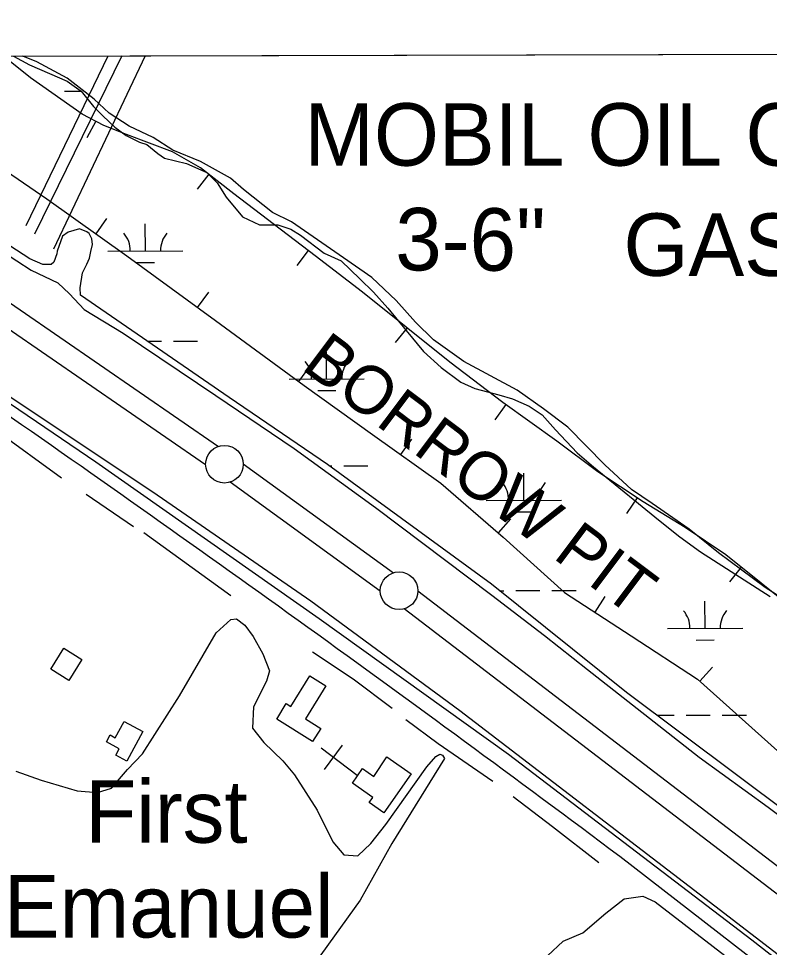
# Model space of a CAD drawing. Extents: x 3355724 to 3393621, y 594744 to 620174.
# Drawn here: x 3372282 to 3373280, y 617160 to 618395 of the extents above; entities that cross this region are included whole.
import ezdxf

# ---------------------------------------------------------------- set-up
doc = ezdxf.new("R2010")
doc.units = 0
for name, color, linetype in [('V-BLDG-OTLN', 7, 'Continuous'), ('V-BORW-IDEN', 7, 'Continuous'), ('V-BORW-LINE', 7, 'Continuous'), ('V-GRID-FRAM', 7, 'Continuous'), ('V-LEVE-TOET', 7, 'Continuous'), ('V-ROAD-CNTR', 7, 'Continuous'), ('V-SITE-OTLN', 7, 'Continuous'), ('V-SITE-OTLN-IDEN', 7, 'Continuous'), ('V-SITE-VEGE', 7, 'Continuous'), ('V-SURV-LINE', 7, 'Continuous'), ('V-TOPO-SHOR', 7, 'Continuous'), ('V-UTIL-IDEN', 7, 'Continuous'), ('V-UTIL-LINE', 7, 'Continuous'), ('V-WETL-SWMP', 7, 'Continuous')]:
    doc.layers.add(name, color=color, linetype=linetype)

msp = doc.modelspace()

# ---------------------------------------------------------------- linework, layer by layer
at = {"layer": 'V-BLDG-OTLN'}
for points in [[(3372342.6, 617558.2), (3372366.7, 617543.1), (3372349.2, 617515.1), (3372325.1, 617530.2)], [(3372673, 617434.2), (3372625.4, 617463.7), (3372638.2, 617484.5), (3372644.2, 617480.7), (3372669.4, 617521.3), (3372690.9, 617507.9), (3372663.8, 617464.2), (3372684.1, 617451.6)], [(3372447.6, 617447.5), (3372426.3, 617408.1), (3372411.8, 617415.9), (3372416.3, 617424.2), (3372399.1, 617433.6), (3372404.1, 617442.8), (3372411, 617439), (3372422.7, 617460.7)], [(3372771.6, 617413.7), (3372804.1, 617391.1), (3372767.9, 617339.3), (3372748.4, 617352.9), (3372753.3, 617359.8), (3372726, 617378.9), (3372739.3, 617398.1), (3372754.3, 617387.6)]]:
    msp.add_lwpolyline(points, close=True, dxfattribs=at)
at = {"layer": 'V-BORW-LINE'}
for p, q in [((3372385, 618258.4), (3372373.3, 618236.3)), ((3372535.1, 618187.9), (3372519.8, 618168.1)), ((3372385.5, 618108.6), (3372399.9, 618129)), ((3372667.2, 618086.4), (3372652, 618066.6)), ((3372520.4, 618010.9), (3372535.1, 618031)), ((3372798.6, 617984), (3372782.9, 617964.5)), ((3372654.7, 617912.3), (3372669.5, 617932.5)), ((3372930.1, 617881.8), (3372915.5, 617861.5)), ((3372790.3, 617815.6), (3372804.8, 617835.9)), ((3373104.2, 617758.1), (3373090.4, 617737.2)), ((3372920, 617711.3), (3372936.4, 617730.1)), ((3373242.6, 617665.7), (3373227, 617646.2)), ((3373048.5, 617605.9), (3373062.1, 617626.8)), ((3373187.6, 617514.3), (3373204.3, 617533))]:
    msp.add_line(p, q, dxfattribs=at)
for points in [[(3372997.7, 617833), (3372926, 617884.8), (3372855.5, 617938.1), (3372797.6, 617984.7), (3372739.6, 618031), (3372676.4, 618079.5), (3372613.1, 618127.9), (3372568.6, 618162.1), (3372524.1, 618196.4), (3372487.1, 618217.9), (3372426, 618240.8), (3372395.6, 618252.7), (3372367, 618267.9), (3372298.1, 618316), (3372262.3, 618344.7)], [(3372212.2, 618228.9), (3372319.8, 618155.2), (3372426.2, 618079.7), (3372544.2, 617993.4), (3372662, 617907), (3372752.8, 617842.2), (3372843.7, 617777.6), (3372926.5, 617705.6), (3373007.9, 617632.2), (3373096.5, 617574.7), (3373184.8, 617516.9), (3373291.1, 617421.7), (3373398.4, 617327.7), (3373494.7, 617255.3), (3373591.4, 617183.5), (3373670.1, 617126.2)], [(3373912.1, 617155.6), (3373904.1, 617173.1), (3373894, 617189.5), (3373865, 617228.4), (3373849, 617246.1), (3373830.8, 617262), (3373786.1, 617292.1), (3373739.7, 617318.7), (3373650.5, 617358.7), (3373606.5, 617379.4), (3373566, 617405.6), (3373489.8, 617466.6), (3373413.8, 617527.8), (3373318.2, 617605), (3373222.4, 617682), (3373168.4, 617718.4), (3373112.5, 617752.7), (3373052, 617792.5), (3372997.7, 617833)]]:
    msp.add_lwpolyline(points, dxfattribs=at)
at = {"layer": 'V-GRID-FRAM'}
msp.add_lwpolyline([(3359807.6, 618312.1), (3391397.2, 618394.8), (3391452.7, 600211.2), (3359847.2, 600128.5), (3359807.6, 618312.1)], dxfattribs=at)
at = {"layer": 'V-LEVE-TOET'}
for points in [[(3375825.8, 615008.1), (3375822, 615015.1), (3375811.4, 615025.5), (3375795.2, 615044.9), (3375674, 615158.8), (3375432.6, 615386.6), (3375213.6, 615584.5), (3374890.6, 615875.4), (3374636, 616096.2), (3374322.2, 616352.3), (3373944.2, 616649.4), (3373708.9, 616836.3), (3373573.2, 616934.7), (3373207.8, 617215.1), (3372868.9, 617474.7), (3372670.8, 617620.4), (3372460.9, 617765.4), (3372217.6, 617927), (3371905.3, 618137.9), (3371607.7, 618305.7), (3371539.6, 618342.8)], [(3372241.5, 618097.5), (3372299.3, 618060.5), (3372334.5, 618043.4), (3372350.3, 618029), (3372369.6, 618008.4), (3372421.3, 617976.8), (3372544.6, 617893.9), (3372648.6, 617823.3), (3372756.8, 617745.1), (3372911.1, 617628.5), (3372981.4, 617575), (3373038.6, 617529.8), (3373186.8, 617413.2), (3373278.4, 617346.7), (3373351.4, 617291.8), (3373522.3, 617160.8), (3373640.1, 617078.6), (3373834.5, 616920.1), (3373917.8, 616857.7), (3374126.6, 616693.8)]]:
    msp.add_lwpolyline(points, dxfattribs=at)
at = {"layer": 'V-ROAD-CNTR'}
msp.add_lwpolyline([(3373922.3, 616629.1), (3373081.6, 617281.1)], dxfattribs=at)
msp.add_arc((3355726.1, 594075.3), 28978, 53.20753, 55.24185, dxfattribs=at)
at = {"layer": 'V-SITE-OTLN'}
for p, q in [((3372712.4, 617429.1), (3372688.5, 617397.1)), ((3372732.5, 617389.1), (3372684.4, 617425.1))]:
    msp.add_line(p, q, dxfattribs=at)
at = {"layer": 'V-SITE-VEGE'}
for p, q in [((3372288.2, 618344.7), (3373371.7, 618347.6)), ((3372306.5, 618337.4), (3372288.2, 618344.7)), ((3372347, 618315.6), (3372306.5, 618337.4)), ((3372382.8, 618287.5), (3372347, 618315.6)), ((3372402.7, 618269), (3372382.8, 618287.5)), ((3372429.5, 618251.9), (3372402.7, 618269)), ((3372461.1, 618236.9), (3372429.5, 618251.9)), ((3372487.3, 618219.8), (3372461.1, 618236.9)), ((3372524.4, 618204.8), (3372487.3, 618219.8)), ((3372564.2, 618182.9), (3372524.4, 618204.8)), ((3372581.4, 618167.8), (3372564.2, 618182.9)), ((3372619.9, 618137.1), (3372581.4, 618167.8)), ((3372645.3, 618124.8), (3372619.9, 618137.1)), ((3372714.1, 618076.9), (3372645.3, 618124.8)), ((3372751.9, 618050.9), (3372714.1, 618076.9)), ((3372784.2, 618020.1), (3372751.9, 618050.9)), ((3372809.7, 617991.3), (3372784.2, 618020.1)), ((3372833.7, 617968), (3372809.7, 617991.3)), ((3372874.3, 617939.3), (3372833.7, 617968)), ((3372945.1, 617901), (3372874.3, 617939.3)), ((3372980.1, 617876.4), (3372945.1, 617901)), ((3373012.4, 617851.8), (3372980.1, 617876.4)), ((3373061.3, 617801.8), (3373012.4, 617851.8)), ((3373097, 617768.9), (3373061.3, 617801.8)), ((3373124.5, 617750.5), (3373097, 617768.9)), ((3373173.3, 617716.3), (3373124.5, 617750.5)), ((3373212.5, 617684.8), (3373173.3, 617716.3)), ((3373274.4, 617638.9), (3373212.5, 617684.8)), ((3373318.4, 617610.9), (3373274.4, 617638.9)), ((3373087.2, 617225.1), (3373111.9, 617228.6)), ((3373111.9, 617228.6), (3373128.4, 617221.1)), ((3373062.6, 617205.8), (3373087.2, 617225.1)), ((3373128.4, 617221.1), (3373279, 617105.4)), ((3373032.4, 617179.7), (3373062.6, 617205.8)), ((3373006.3, 617168.6), (3373032.4, 617179.7)), ((3372985.1, 617149.4), (3373006.3, 617168.6))]:
    msp.add_line(p, q, dxfattribs=at)
for points in [[(3372360.3, 617368.4), (3372387.3, 617366.4), (3372405.9, 617371.9), (3372427.3, 617396.9), (3372447.3, 617417.7), (3372496.2, 617494.6), (3372545.2, 617578.4), (3372564.5, 617596.4), (3372572.1, 617597.1), (3372583.2, 617588.8), (3372594.3, 617573.6), (3372606.8, 617550.8), (3372615.8, 617528), (3372611.7, 617514.2), (3372594.5, 617480.3), (3372593.2, 617451.9), (3372608.4, 617432.6), (3372633.4, 617408.4), (3372649.3, 617389.8), (3372679.2, 617342.8), (3372700, 617300.7), (3372714.6, 617283.4), (3372733.3, 617282.1), (3372750.5, 617298.7), (3372770.5, 617323.7), (3372825, 617400.6), (3372836.7, 617414.4), (3372842.3, 617417.2), (3372845.7, 617415.8), (3372848.5, 617411.7), (3372778.2, 617298.8), (3372736.2, 617223.3), (3372676.2, 617139.5)], [(3372278.6, 617394.5), (3372312.5, 617382.8), (3372360.3, 617368.4)]]:
    msp.add_lwpolyline(points, dxfattribs=at)
at = {"layer": 'V-SURV-LINE'}
for points in [[(3372073.1, 618153.2), (3372548, 617826.3)], [(3372531, 617801.6), (3372056.1, 618128.5)], [(3372581, 617803), (3372780.7, 617658.3)], [(3372763.1, 617634), (3372563.4, 617778.8)], [(3372813, 617634.2), (3374266.5, 616522.3)], [(3374248.3, 616498.4), (3372794.8, 617610.4)]]:
    msp.add_lwpolyline(points, dxfattribs=at)
for centre in [(3372556, 617802.6), (3372788, 617634.5)]:
    msp.add_circle(centre, 25, dxfattribs=at)
at = {"layer": 'V-TOPO-SHOR'}
for p, q in [((3372435.1, 617719.5), (3372372.2, 617762.2)), ((3372564.5, 617627.9), (3372449, 617711.2))]:
    msp.add_line(p, q, dxfattribs=at)
for points in [[(3373700.9, 616823.9), (3373531.4, 616955.4), (3373256.7, 617170.3), (3372933.6, 617416.8), (3372681.8, 617597.2), (3372385, 617805.1), (3372112.4, 617990.3), (3372052.9, 618033), (3371907, 618129.3), (3371642.1, 618279.3), (3371524.9, 618342.7)], [(3372339.7, 617784.2), (3372252.5, 617846.9), (3372200.6, 617884.7)], [(3372779, 617477.9), (3372727.1, 617517.1), (3372673.1, 617552.9)], [(3372912.5, 617380.8), (3372839.9, 617431), (3372797, 617462.7)], [(3373053.6, 617272.7), (3372992.1, 617320.9), (3372939.5, 617360.8)]]:
    msp.add_lwpolyline(points, dxfattribs=at)
at = {"layer": 'V-UTIL-LINE'}
for points in [[(3372401.1, 618345), (3372292.1, 618119.2)], [(3372419.5, 618345.1), (3372303.8, 618108.5)], [(3372450.5, 618345.2), (3372329, 618088.2)]]:
    msp.add_lwpolyline(points, dxfattribs=at)
for centre, radius, start, end in [((3379211.1, 615392.4), 7422.5, 156.55966774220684, 156.55967343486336), ((3379441.7, 615177.2), 7703.7, 155.71879, 155.71881), ((3378511.6, 615620.7), 6645.3, 155.79587, 155.79588)]:
    msp.add_arc(centre, radius, start, end, dxfattribs=at)
at = {"layer": 'V-WETL-SWMP'}
for p, q in [((3372275.6, 618344.7), (3372296.8, 618333.3)), ((3372296.8, 618333.3), (3372323.6, 618321.7)), ((3372323.6, 618321.7), (3372347, 618311.5)), ((3372347, 618311.5), (3372365.6, 618298.5)), ((3372343.5, 618298.4), (3372365.6, 618298.4)), ((3372365.6, 618298.5), (3372382.1, 618277.9)), ((3372382.1, 618277.9), (3372394.5, 618265.6)), ((3372394.5, 618265.6), (3372410.3, 618250.5)), ((3372410.3, 618250.5), (3372425.5, 618239.6)), ((3372425.5, 618239.6), (3372443.3, 618230.7)), ((3372443.3, 618230.7), (3372452.9, 618227.3)), ((3372452.9, 618227.3), (3372467.4, 618215.6)), ((3372467.4, 618215.6), (3372476.3, 618209.5)), ((3372476.3, 618209.5), (3372505.8, 618202)), ((3372505.8, 618202), (3372532.6, 618190.4)), ((3372532.6, 618190.4), (3372546.4, 618176.7)), ((3372546.4, 618176.7), (3372558.1, 618157.5)), ((3372558.1, 618157.5), (3372580.1, 618131.5)), ((3372580.1, 618131.5), (3372602.8, 618120.5)), ((3372450.9, 618086), (3372450.8, 618122)), ((3372602.8, 618120.5), (3372626.8, 618120.6)), ((3372626.8, 618120.6), (3372644, 618115.1)), ((3372297.6, 618075.3), (3372248.8, 618106.8)), ((3372340.7, 618105.6), (3372333.9, 618085.7)), ((3372348.3, 618111.1), (3372340.7, 618105.6)), ((3372363.4, 618115.3), (3372348.3, 618111.1)), ((3372373, 618111.2), (3372363.4, 618115.3)), ((3372376.4, 618109.1), (3372373, 618111.2)), ((3372379.9, 618102.3), (3372376.4, 618109.1)), ((3372644, 618115.1), (3372657, 618106.9)), ((3372657, 618106.9), (3372688.7, 618083)), ((3372378.5, 618085.1), (3372380.6, 618094.7)), ((3372380.6, 618094.7), (3372379.9, 618102.3)), ((3372333.2, 618082.2), (3372329.1, 618071.3)), ((3372333.9, 618085.7), (3372333.2, 618082.2)), ((3372376.5, 618076.2), (3372378.5, 618085.1)), ((3372400.9, 618085.9), (3372500.9, 618086.2)), ((3372688.7, 618083), (3372711.3, 618072.8)), ((3372314.7, 618067.8), (3372297.6, 618075.3)), ((3372325.7, 618067.8), (3372314.7, 618067.8)), ((3372329.1, 618071.3), (3372325.7, 618067.8)), ((3372367.6, 618056.9), (3372373.1, 618068.6)), ((3372373.1, 618068.6), (3372376.5, 618076.2)), ((3372439, 618070.6), (3372463, 618070.6)), ((3372711.3, 618072.8), (3372736.1, 618048.8)), ((3372364.2, 618037), (3372367.6, 618056.9)), ((3372736.1, 618048.8), (3372754, 618031)), ((3372364.9, 618027.4), (3372364.2, 618037)), ((3372754, 618031), (3372773.2, 618009.8)), ((3372562.2, 617891.3), (3372364.9, 618027.4)), ((3372773.2, 618009.8), (3372797.3, 617980.3)), ((3372797.3, 617980.3), (3372820.7, 617952.2)), ((3372454, 617966), (3372472.4, 617966)), ((3372488.4, 617966.1), (3372520.4, 617966.1)), ((3372691.8, 617915.8), (3372691.7, 617951.8)), ((3372820.7, 617952.2), (3372844.1, 617931)), ((3372844.1, 617931), (3372870.2, 617911.8)), ((3372641.8, 617915.7), (3372741.8, 617916)), ((3372870.2, 617911.8), (3372888.8, 617903)), ((3372679.9, 617900.4), (3372703.9, 617900.4)), ((3372888.8, 617903), (3372920.4, 617894.8)), ((3372920.4, 617894.8), (3372938.9, 617889.4)), ((3372692.8, 617802.4), (3372562.2, 617891.3)), ((3372938.9, 617889.4), (3372960.9, 617879.8)), ((3372960.9, 617879.8), (3372978.1, 617868.2)), ((3372978.1, 617868.2), (3372996, 617848.3)), ((3372996, 617848.3), (3373024.9, 617817.5)), ((3373024.9, 617817.5), (3373046.2, 617799)), ((3372910.7, 617643), (3372692.8, 617802.4)), ((3372695.5, 617800.4), (3372698.7, 617800.4)), ((3372714.7, 617800.5), (3372746.7, 617800.6)), ((3373046.2, 617799), (3373079.9, 617771.6)), ((3372953.7, 617754.7), (3372953.6, 617790.7)), ((3373079.9, 617771.6), (3373106, 617750.4)), ((3372903.7, 617754.5), (3373003.7, 617754.8)), ((3373106, 617750.4), (3373132.8, 617728.5)), ((3372941.7, 617739.2), (3372965.7, 617739.3)), ((3373132.8, 617728.5), (3373161, 617705.9)), ((3373161, 617705.9), (3373188.5, 617686.1)), ((3373188.5, 617686.1), (3373281.3, 617626.6)), ((3373090.2, 617499.3), (3372910.7, 617643)), ((3372921.3, 617634.5), (3372927.2, 617634.5)), ((3372943.2, 617634.6), (3372975.2, 617634.7)), ((3372991.2, 617634.7), (3373023.2, 617634.8)), ((3373194.6, 617584.5), (3373194.5, 617620.5)), ((3373144.6, 617584.4), (3373244.6, 617584.6)), ((3373182.7, 617569), (3373206.7, 617569.1)), ((3373315.7, 617330.3), (3373090.2, 617499.3)), ((3373130.7, 617468.9), (3373153.5, 617468.9)), ((3373169.5, 617469), (3373201.5, 617469.1)), ((3373217.5, 617469.1), (3373249.5, 617469.2))]:
    msp.add_line(p, q, dxfattribs=at)
for centre, start, end in [((3372395.7, 618086.4), 359.3782, 40.9218), ((3372506.2, 618086.6), 139.3782, 180.9218), ((3372636.6, 617916.2), 359.3782, 40.9218), ((3372747.1, 617916.5), 139.3782, 180.9218), ((3372898.5, 617755), 359.3782, 40.9218), ((3373008.9, 617755.3), 139.3782, 180.9218), ((3373139.4, 617584.8), 359.3782, 40.9218), ((3373249.9, 617585.1), 139.3782, 180.9218)]:
    msp.add_arc(centre, 35.2, start, end, dxfattribs=at)

# ---------------------------------------------------------------- texts
at = {"layer": 'V-BORW-IDEN'}
msp.add_text('BORROW PIT', height=64, rotation=323.0794, dxfattribs=at).set_placement((3372656.5, 617930.1))
at = {"layer": 'V-SITE-OTLN-IDEN'}
for s, p in [('First', (3372371, 617299.6)), ('Emanuel', (3372263, 617173.6))]:
    msp.add_text(s, height=83, dxfattribs=at).set_placement(p)
at = {"layer": 'V-UTIL-IDEN'}
for s, p in [('MOBIL OIL CORP.', (3372662.2, 618199.3)), (' GAS PIPELINES', (3373055.4, 618052.9))]:
    msp.add_text(s, height=83, dxfattribs=at).set_placement(p)
msp.add_text('3-6"', height=83, rotation=359.8065, dxfattribs=at).set_placement((3372782.9, 618060.2))

doc.saveas('drawing.dxf')
